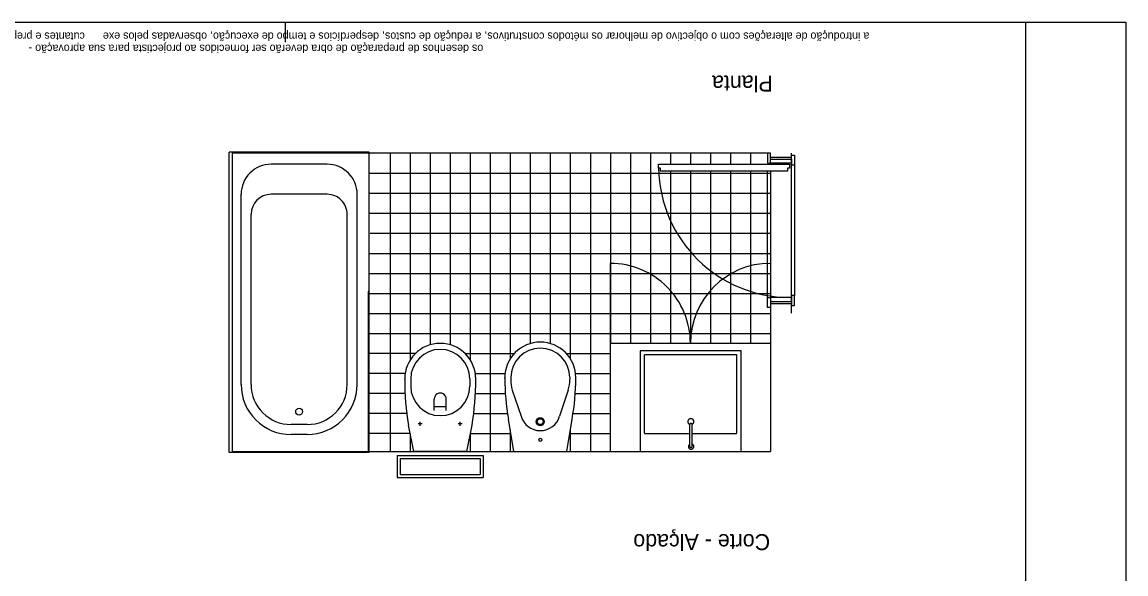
# Model space of a CAD drawing. Extents: x 1288.3 to 1299.9, y -285.2 to -279.3.
# Drawn here: x 1294.34 to 1299.85, y -282.04 to -279.28 of the extents above; entities that cross this region are included whole.
import ezdxf

# ---------------------------------------------------------------- set-up
doc = ezdxf.new("R2010")
doc.units = 0
for name, color, linetype in [('Level 1', 7, 'Continuous'), ('Level 10', 7, 'Continuous'), ('Level 11', 7, 'Continuous'), ('Level 13', 7, 'Continuous'), ('Level 2', 7, 'Continuous'), ('Level 36', 7, 'Continuous'), ('Level 4', 7, 'Continuous'), ('Level 60', 7, 'Continuous'), ('Level 62', 7, 'Continuous')]:
    doc.layers.add(name, color=color, linetype=linetype)

msp = doc.modelspace()

# ---------------------------------------------------------------- linework, layer by layer
at = {"layer": 'Level 1'}
for p, q in [((1295.3885, -279.9346), (1295.3885, -281.4246)), ((1298.0785, -279.9346), (1295.3885, -279.9346)), ((1298.0785, -279.9546), (1298.0785, -279.9346)), ((1298.0785, -279.9546), (1298.1835, -279.9546)), ((1298.1835, -279.9546), (1298.1835, -279.9346)), ((1298.0785, -280.6846), (1298.0785, -281.4246)), ((1298.0785, -280.6846), (1298.0885, -280.6846)), ((1298.0785, -280.6846), (1298.1835, -280.6846)), ((1298.1735, -280.6846), (1298.1835, -280.6846)), ((1298.1835, -280.7336), (1298.1835, -280.6846)), ((1295.3885, -281.4246), (1298.0785, -281.4246))]:
    msp.add_line(p, q, dxfattribs=at)
at = {"layer": 'Level 10'}
for p, q in [((1296.1785, -279.9346), (1296.1785, -281.4246)), ((1296.2785, -279.9346), (1296.2785, -280.9669)), ((1296.3785, -279.9346), (1296.3785, -280.8915)), ((1296.4785, -279.9346), (1296.4785, -280.8915)), ((1296.5785, -279.9346), (1296.5785, -280.9669)), ((1296.6785, -279.9346), (1296.6785, -281.4246)), ((1296.7785, -279.9346), (1296.7785, -280.9607)), ((1296.8785, -279.9346), (1296.8785, -280.8853)), ((1296.9785, -279.9346), (1296.9785, -280.8853)), ((1297.0785, -279.9346), (1297.0785, -280.9607)), ((1297.1785, -279.9346), (1297.1785, -281.4246)), ((1297.2785, -279.9346), (1297.2785, -280.8846)), ((1297.3785, -279.9346), (1297.3785, -280.8846)), ((1297.4785, -279.9346), (1297.4785, -280.8846)), ((1297.5785, -279.9346), (1297.5785, -279.9896)), ((1297.6785, -279.9346), (1297.6785, -279.9896)), ((1297.7785, -279.9346), (1297.7785, -279.9896)), ((1297.8785, -279.9346), (1297.8785, -279.9896)), ((1297.9785, -279.9346), (1297.9785, -279.9896)), ((1298.1835, -280.6546), (1298.1835, -279.9896)), ((1296.0735, -280.0346), (1298.0785, -280.0346)), ((1297.5785, -280.0246), (1297.5785, -280.8846)), ((1297.6785, -280.0246), (1297.6785, -280.8846)), ((1297.7785, -280.0246), (1297.7785, -280.8846)), ((1297.8785, -280.0246), (1297.8785, -280.8846)), ((1297.9785, -280.0246), (1297.9785, -280.8846)), ((1298.0785, -280.0246), (1298.0785, -280.6546)), ((1296.0735, -280.1346), (1298.0785, -280.1346)), ((1296.0735, -280.2346), (1298.0785, -280.2346)), ((1296.0787, -280.3346), (1298.0785, -280.3346)), ((1296.0735, -280.4346), (1298.0785, -280.4346)), ((1296.0735, -280.5346), (1298.0785, -280.5346)), ((1296.0735, -280.6346), (1298.0785, -280.6346)), ((1296.0735, -280.7346), (1298.0785, -280.7346)), ((1296.0735, -280.8346), (1298.0785, -280.8346)), ((1296.3046, -280.9346), (1296.0735, -280.9346)), ((1296.5523, -280.9346), (1296.7986, -280.9346)), ((1297.0584, -280.9346), (1297.2785, -280.9346)), ((1296.2531, -281.0346), (1296.0735, -281.0346)), ((1296.6039, -281.0346), (1296.7522, -281.0346)), ((1297.1047, -281.0346), (1297.2785, -281.0346)), ((1296.2527, -281.1346), (1296.0735, -281.1346)), ((1296.6043, -281.1346), (1296.7535, -281.1346)), ((1297.1034, -281.1346), (1297.2785, -281.1346)), ((1296.2613, -281.2346), (1296.0735, -281.2346)), ((1296.5957, -281.2346), (1296.7648, -281.2346)), ((1297.0922, -281.2346), (1297.2785, -281.2346)), ((1296.2781, -281.3346), (1296.0735, -281.3346)), ((1296.2785, -281.3367), (1296.2785, -281.4246)), ((1296.5785, -281.3369), (1296.5785, -281.4246)), ((1296.5789, -281.3346), (1296.7814, -281.3346)), ((1296.7785, -281.3167), (1296.7785, -281.4246)), ((1297.0755, -281.3346), (1297.2785, -281.3346)), ((1297.0785, -281.3167), (1297.0785, -281.4246))]:
    msp.add_line(p, q, dxfattribs=at)
at = {"layer": 'Level 11'}
for p, q in [((1296.0735, -279.9296), (1295.3735, -279.9296)), ((1295.3735, -281.4296), (1295.3735, -279.9296)), ((1296.0735, -281.4296), (1296.0735, -279.9296)), ((1295.8635, -279.9896), (1295.5835, -279.9896)), ((1295.4335, -281.0896), (1295.4335, -280.1396)), ((1295.8635, -280.1396), (1295.5835, -280.1396)), ((1296.0135, -281.0896), (1296.0135, -280.1396)), ((1295.4835, -281.0896), (1295.4835, -280.2396)), ((1295.9635, -281.0896), (1295.9635, -280.2396)), ((1297.4275, -280.9211), (1297.4275, -281.4202)), ((1297.9318, -280.9211), (1297.4275, -280.9211)), ((1297.4486, -281.3307), (1297.4486, -280.9421)), ((1297.9108, -280.9422), (1297.4486, -280.9421)), ((1297.9108, -281.3307), (1297.9108, -280.9422)), ((1297.9318, -281.4202), (1297.9318, -280.9211)), ((1296.251, -281.0652), (1296.251, -281.0615)), ((1296.281, -281.0618), (1296.281, -281.0979)), ((1296.576, -281.0618), (1296.576, -281.0979)), ((1296.606, -281.0652), (1296.606, -281.0615)), ((1296.751, -281.0589), (1296.751, -281.0553)), ((1296.781, -281.0555), (1296.781, -281.0636)), ((1297.076, -281.0555), (1297.076, -281.0636)), ((1297.106, -281.0589), (1297.106, -281.0553)), ((1296.7887, -281.1185), (1296.8323, -281.2477)), ((1297.0683, -281.1185), (1297.0246, -281.2477)), ((1296.3985, -281.2198), (1296.3985, -281.1625)), ((1296.4585, -281.2198), (1296.4585, -281.1626)), ((1296.4585, -281.2021), (1296.3985, -281.2021)), ((1296.3385, -281.2861), (1296.3185, -281.2861)), ((1296.3285, -281.2961), (1296.3285, -281.2761)), ((1296.5385, -281.2861), (1296.5185, -281.2861)), ((1296.5285, -281.2961), (1296.5285, -281.2761)), ((1296.7962, -281.4243), (1296.7695, -281.2622)), ((1297.0608, -281.4243), (1297.0874, -281.2622)), ((1295.7635, -281.2896), (1295.6835, -281.2896)), ((1295.7635, -281.3396), (1295.6835, -281.3396)), ((1296.2962, -281.4246), (1296.2695, -281.2922)), ((1296.5608, -281.4246), (1296.5875, -281.2922)), ((1297.4529, -281.335), (1297.6757, -281.335)), ((1297.6757, -281.3995), (1297.6757, -281.29)), ((1297.687, -281.3995), (1297.687, -281.29)), ((1297.687, -281.335), (1297.9064, -281.335)), ((1296.0735, -281.4296), (1295.3735, -281.4296)), ((1296.2135, -281.4446), (1296.2135, -281.5546)), ((1296.2135, -281.4446), (1296.6435, -281.4446)), ((1296.5608, -281.4246), (1296.2962, -281.4246)), ((1296.6435, -281.4446), (1296.6435, -281.5546)), ((1296.7962, -281.4243), (1297.0608, -281.4243)), ((1297.4319, -281.4246), (1297.9275, -281.4246)), ((1296.2285, -281.4596), (1296.6285, -281.4596)), ((1296.2285, -281.4596), (1296.2285, -281.5396)), ((1296.6285, -281.4596), (1296.6285, -281.5396)), ((1296.2135, -281.5546), (1296.6435, -281.5546)), ((1296.2285, -281.5396), (1296.6285, -281.5396))]:
    msp.add_line(p, q, dxfattribs=at)
for centre, radius in [((1295.7235, -281.2252), 0.0173), ((1296.9285, -281.2755), 0.02), ((1296.9285, -281.2755), 0.0146), ((1296.9285, -281.3663), 0.00766)]:
    msp.add_circle(centre, radius, dxfattribs=at)
for centre, radius, start, end in [((1295.5835, -280.1396), 0.15, 89.9999, 180.0002), ((1295.8635, -280.1396), 0.15, 360, 90), ((1295.5835, -280.2396), 0.1, 90.0001, 179.9999), ((1295.8635, -280.2396), 0.1, 360, 90.0001), ((1296.4285, -281.0618), 0.1775, 0.0002, 179.9999), ((1296.9285, -281.0556), 0.1775, 0.0001, 179.9998), ((1296.4285, -281.0618), 0.1475, 0.0002, 179.9999), ((1296.9285, -281.0556), 0.1475, 0.0001, 179.9998), ((1297.651, -281.0652), 1.4, 179.9999, 189.3345), ((1295.206, -281.0652), 1.4, 350.6656, 0.0002), ((1296.981, -281.0637), 0.2, 179.9994, 195.9307), ((1296.876, -281.0637), 0.2, 344.0681, 359.9983), ((1295.6835, -281.0896), 0.25, 180, 270.0001), ((1295.6835, -281.0896), 0.2, 180, 270), ((1295.7635, -281.0896), 0.25, 269.9999, 359.9999), ((1295.7635, -281.0896), 0.2, 270, 0), ((1296.4285, -281.0979), 0.1475, 180.0002, 359.9999), ((1296.4285, -281.1628), 0.03, 359.9995, 180.0013), ((1296.9285, -281.2203), 0.1, 195.8047, 344.0683), ((1297.681, -281.2755), 0.015, 293.6307, 249.2833), ((1297.6814, -281.2894), 0.00566, 354.0176, 185.9962), ((1297.4529, -281.3307), 0.00438, 180, 270), ((1297.9064, -281.3307), 0.00438, 270, 0), ((1297.6818, -281.4001), 0.0135, 116.7199, 67.3909), ((1297.4319, -281.4202), 0.00438, 180, 270), ((1297.6814, -281.4001), 0.00566, 174.0038, 5.9824), ((1297.9275, -281.4202), 0.00438, 270, 0)]:
    msp.add_arc(centre, radius, start, end, dxfattribs=at)
for centre, major_axis, start_param, end_param in [((1298.151, -281.0589), (-1.4, 0), 6.283183, 6.446102), ((1295.706, -281.0589), (1.4, 0), 6.120269, 6.283187)]:
    msp.add_ellipse(centre, major_axis=major_axis, ratio=0.895428, start_param=start_param, end_param=end_param, dxfattribs=at)
at = {"layer": 'Level 13'}
for p, q in [((1298.0635, -279.9346), (1298.0635, -279.9846)), ((1298.0785, -279.9346), (1298.0635, -279.9346)), ((1298.0785, -279.9846), (1298.0785, -279.9346)), ((1298.0785, -279.9646), (1298.1835, -279.9646)), ((1298.0785, -279.9846), (1298.0785, -279.9646)), ((1298.1835, -279.9946), (1298.1835, -279.9446)), ((1298.1835, -279.9446), (1298.1985, -279.9446)), ((1298.1835, -279.9646), (1298.1835, -279.9946)), ((1298.1985, -279.9446), (1298.1985, -279.9946)), ((1297.5192, -279.9896), (1298.1742, -279.9896)), ((1297.5192, -280.0096), (1297.5192, -279.9896)), ((1297.5292, -280.0096), (1297.5194, -280.0096)), ((1297.5292, -280.0246), (1297.5292, -280.0096)), ((1298.0635, -279.9846), (1298.0785, -279.9846)), ((1298.1835, -279.9846), (1298.0785, -279.9846)), ((1298.1642, -280.0096), (1298.1642, -280.0246)), ((1298.1742, -280.0096), (1298.1642, -280.0096)), ((1298.1742, -279.9896), (1298.1742, -280.0096)), ((1298.1985, -279.9946), (1298.1835, -279.9946)), ((1298.1642, -280.0246), (1297.5292, -280.0246)), ((1298.0635, -280.7046), (1298.0635, -280.6546)), ((1298.0635, -280.6546), (1298.0785, -280.6546)), ((1298.1835, -280.6546), (1298.0785, -280.6546)), ((1298.0785, -280.6546), (1298.0785, -280.6746)), ((1298.0785, -280.6546), (1298.0785, -280.7046)), ((1298.0785, -280.6746), (1298.1835, -280.6746)), ((1298.1835, -280.6746), (1298.1835, -280.6446)), ((1298.1985, -280.6446), (1298.1835, -280.6446)), ((1298.1835, -280.6446), (1298.1835, -280.6946)), ((1298.1985, -280.6946), (1298.1985, -280.6446)), ((1298.0785, -280.7046), (1298.0635, -280.7046)), ((1298.1835, -280.6946), (1298.1985, -280.6946))]:
    msp.add_line(p, q, dxfattribs=at)
at = {"layer": 'Level 2'}
for p, q in [((1298.0785, -280.8846), (1297.2785, -280.8846)), ((1297.2785, -281.4246), (1297.2785, -280.8846)), ((1298.0785, -280.8846), (1298.0785, -281.4246))]:
    msp.add_line(p, q, dxfattribs=at)
at = {"layer": 'Level 36'}
for p, q in [((1296.0735, -280.6246), (1296.0685, -280.6246)), ((1296.0685, -280.6246), (1296.0685, -281.4246)), ((1296.0735, -281.4246), (1296.0735, -280.6246))]:
    msp.add_line(p, q, dxfattribs=at)
at = {"layer": 'Level 4'}
for p, q in [((1298.1985, -279.9946), (1298.1985, -280.6446)), ((1298.0635, -280.6546), (1298.0635, -280.0246)), ((1297.2785, -280.8846), (1297.2785, -280.4846))]:
    msp.add_line(p, q, dxfattribs=at)
for centre, start, end in [((1297.2785, -280.8846), 0, 90.0011), ((1298.0785, -280.8846), 90.0011, 180)]:
    msp.add_arc(centre, 0.4, start, end, dxfattribs=at)
msp.add_ellipse((1298.1742, -279.996), major_axis=(0, 0.6586), ratio=0.994272, start_param=1.591512, end_param=3.141593, dxfattribs=at)
at = {"layer": 'Level 62'}
for p, q in [((1295.655, -279.3793), (1295.655, -279.2793)), ((1299.3546, -285.2193), (1299.3546, -279.2793))]:
    msp.add_line(p, q, dxfattribs=at)
msp.add_lwpolyline([(1299.8546, -279.2793), (1299.8546, -285.2193), (1288.255, -285.2193), (1288.255, -279.2793)], close=True, dxfattribs=at)

# ---------------------------------------------------------------- texts
at = {"layer": 'Level 60'}
for s, p in [('Planta', (1298.0897, -279.5463)), ('Corte - Alçado', (1298.0769, -281.8371))]:
    msp.add_text(s, height=0.08, rotation=180, dxfattribs=at).set_placement(p)
at = {"layer": 'Level 62'}
for s, height, p in [('cutantes e preparadores da obra deverão ser sugeridas. não poderão no entanto ser implementadas sem o consentimento expresso dos responsáveis pela arquitectura', 0.0399996, (1294.6528, -279.3313)), ('a introdução de alterações com o objectivo de melhorar os métodos construtivos, a redução de custos, desperdícios e tempo de execução, observadas pelos exe', 0.0399996, (1298.5726, -279.3313)), ('os desenhos de preparação de obra deverão ser fornecidos ao projectista para sua aprovação -', 0.04, (1296.6436, -279.3923))]:
    msp.add_text(s, height=height, rotation=180, dxfattribs=at).set_placement(p)

doc.saveas('drawing.dxf')
